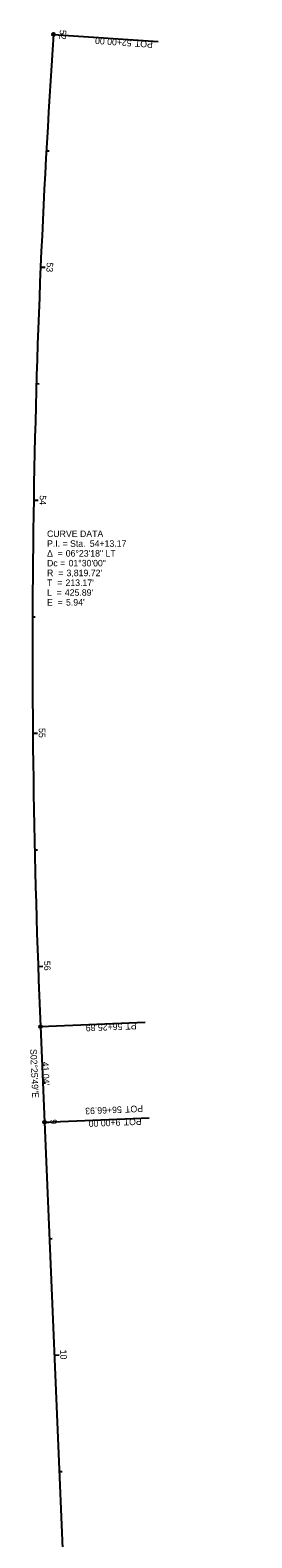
# Model space of a CAD drawing. Extents: x 2047512 to 2047652, y 283295 to 285863.
# Drawn here: x 2047512 to 2047607, y 285217 to 285863 of the extents above; entities that cross this region are included whole.
import ezdxf

# ---------------------------------------------------------------- set-up
doc = ezdxf.new("R2010")
doc.units = 0
for name, color, linetype in [('RW_X_CL', 7, 'Continuous'), ('RW_X_CL_100_Bearings', 7, 'Continuous'), ('RW_X_CL_100_Cardinal_Points', 7, 'Continuous'), ('RW_X_CL_100_Curve_Data', 7, 'Continuous'), ('RW_X_CL_100_Distances', 7, 'Continuous'), ('RW_X_CL_100_Stations', 7, 'Continuous')]:
    doc.layers.add(name, color=color, linetype=linetype)

msp = doc.modelspace()

# ---------------------------------------------------------------- linework, layer by layer
at = {"layer": 'RW_X_CL'}
for p, q in [((2047516.21, 285435.88), (2047517.95, 285394.88)), ((2047516.21, 285435.88), (2047517.95, 285394.88)), ((2047517.95, 285394.88), (2047607, 283296.77)), ((2047517.95, 285394.88), (2047607, 283296.77))]:
    msp.add_line(p, q, dxfattribs=at)
msp.add_arc((2051332.5, 285597.86), 3819.72, 176.04201, 182.43035, dxfattribs=at)
msp.add_arc((2051332.5, 285597.86), 3819.72, 176.04201, 182.43035, dxfattribs=at)
at = {"layer": 'RW_X_CL_100_Cardinal_Points'}
for p, q in [((2047521.88, 285861.51), (2047566.78, 285858.41)), ((2047516.21, 285435.88), (2047561.17, 285437.79)), ((2047517.95, 285394.88), (2047562.91, 285396.79)), ((2047517.95, 285394.88), (2047562.91, 285396.79))]:
    msp.add_line(p, q, dxfattribs=at)
for centre in [(2047521.88, 285861.51), (2047516.21, 285435.88), (2047517.95, 285394.88), (2047517.95, 285394.88)]:
    msp.add_circle(centre, 0.6, dxfattribs=at)
at = {"layer": 'RW_X_CL_100_Stations'}
for p, q in [((2047521.88, 285861.51), (2047523.88, 285861.38)), ((2047518.76, 285811.61), (2047519.96, 285811.54)), ((2047516.29, 285761.67), (2047518.29, 285761.59)), ((2047514.47, 285711.71), (2047515.67, 285711.67)), ((2047513.31, 285661.72), (2047515.31, 285661.69)), ((2047512.8, 285611.72), (2047514, 285611.72)), ((2047512.94, 285561.72), (2047514.94, 285561.74)), ((2047513.74, 285511.73), (2047514.94, 285511.76)), ((2047515.2, 285461.75), (2047517.2, 285461.82)), ((2047517.23, 285411.79), (2047518.43, 285411.84)), ((2047517.95, 285394.88), (2047519.95, 285394.96)), ((2047520.07, 285344.92), (2047521.27, 285344.98)), ((2047522.19, 285294.97), (2047524.19, 285295.05)), ((2047524.31, 285245.01), (2047525.51, 285245.07))]:
    msp.add_line(p, q, dxfattribs=at)

# ---------------------------------------------------------------- texts
at = {"layer": 'RW_X_CL_100_Bearings'}
msp.add_text('S02°25\'49"E', height=2.8, rotation=272.43035, dxfattribs=at).set_placement((2047511.81, 285426.24))
at = {"layer": 'RW_X_CL_100_Cardinal_Points'}
for s, rotation, p in [('52+00.00', 176.04201, (2047555.46, 285859.14)), ('POT', 176.04201, (2047564.57, 285858.51)), ('56+25.89', 182.43035, (2047551.33, 285437.33)), ('PT', 182.43035, (2047557.42, 285437.58)), ('56+66.93', 182.43035, (2047551.09, 285401.73)), ('POT', 182.43035, (2047559.62, 285396.6)), ('POT', 182.43035, (2047560.21, 285402.12)), ('9+00.00', 182.43035, (2047550.5, 285396.21))]:
    msp.add_text(s, height=2.8, rotation=rotation, dxfattribs=at).set_placement(p)
at = {"layer": 'RW_X_CL_100_Curve_Data'}
for s, p in [('CURVE DATA', (2047519.05, 285645.9)), ('P.I. = Sta. ', (2047519.05, 285641.7)), ('54+13.17', (2047537.41, 285641.7)), ('Δ  = ', (2047519.05, 285637.5)), ('Dc = ', (2047519.05, 285633.3)), ('06°23\'18" LT', (2047527.07, 285637.5)), ('01°30\'00"', (2047528.28, 285633.3)), ('R  = ', (2047519.05, 285629.1)), ("3,819.72'", (2047527.41, 285629.1)), ('T  = ', (2047519.05, 285624.9)), ('L  = ', (2047519.05, 285620.7)), ("425.89'", (2047526.69, 285620.7)), ("213.17'", (2047526.98, 285624.9)), ('E  = ', (2047519.05, 285616.5)), ("5.94'", (2047527.2, 285616.5))]:
    msp.add_text(s, height=2.8, dxfattribs=at).set_placement(p)
at = {"layer": 'RW_X_CL_100_Distances'}
msp.add_text("41.04'", height=2.8, rotation=272.43035, dxfattribs=at).set_placement((2047516.9, 285420.78))
at = {"layer": 'RW_X_CL_100_Stations'}
for s, rotation, p in [('52', 266.04201, (2047524.57, 285863.52)), ('53', 267.542, (2047518.93, 285763.74)), ('54', 269.042, (2047515.89, 285663.83)), ('55', 270.542, (2047515.47, 285563.95)), ('56', 272.042, (2047517.67, 285464.04)), ('9', 272.43035, (2047520.45, 285396.06)), ('10', 272.43035, (2047524.64, 285297.27))]:
    msp.add_text(s, height=2.8, rotation=rotation, dxfattribs=at).set_placement(p)

doc.saveas('drawing.dxf')
